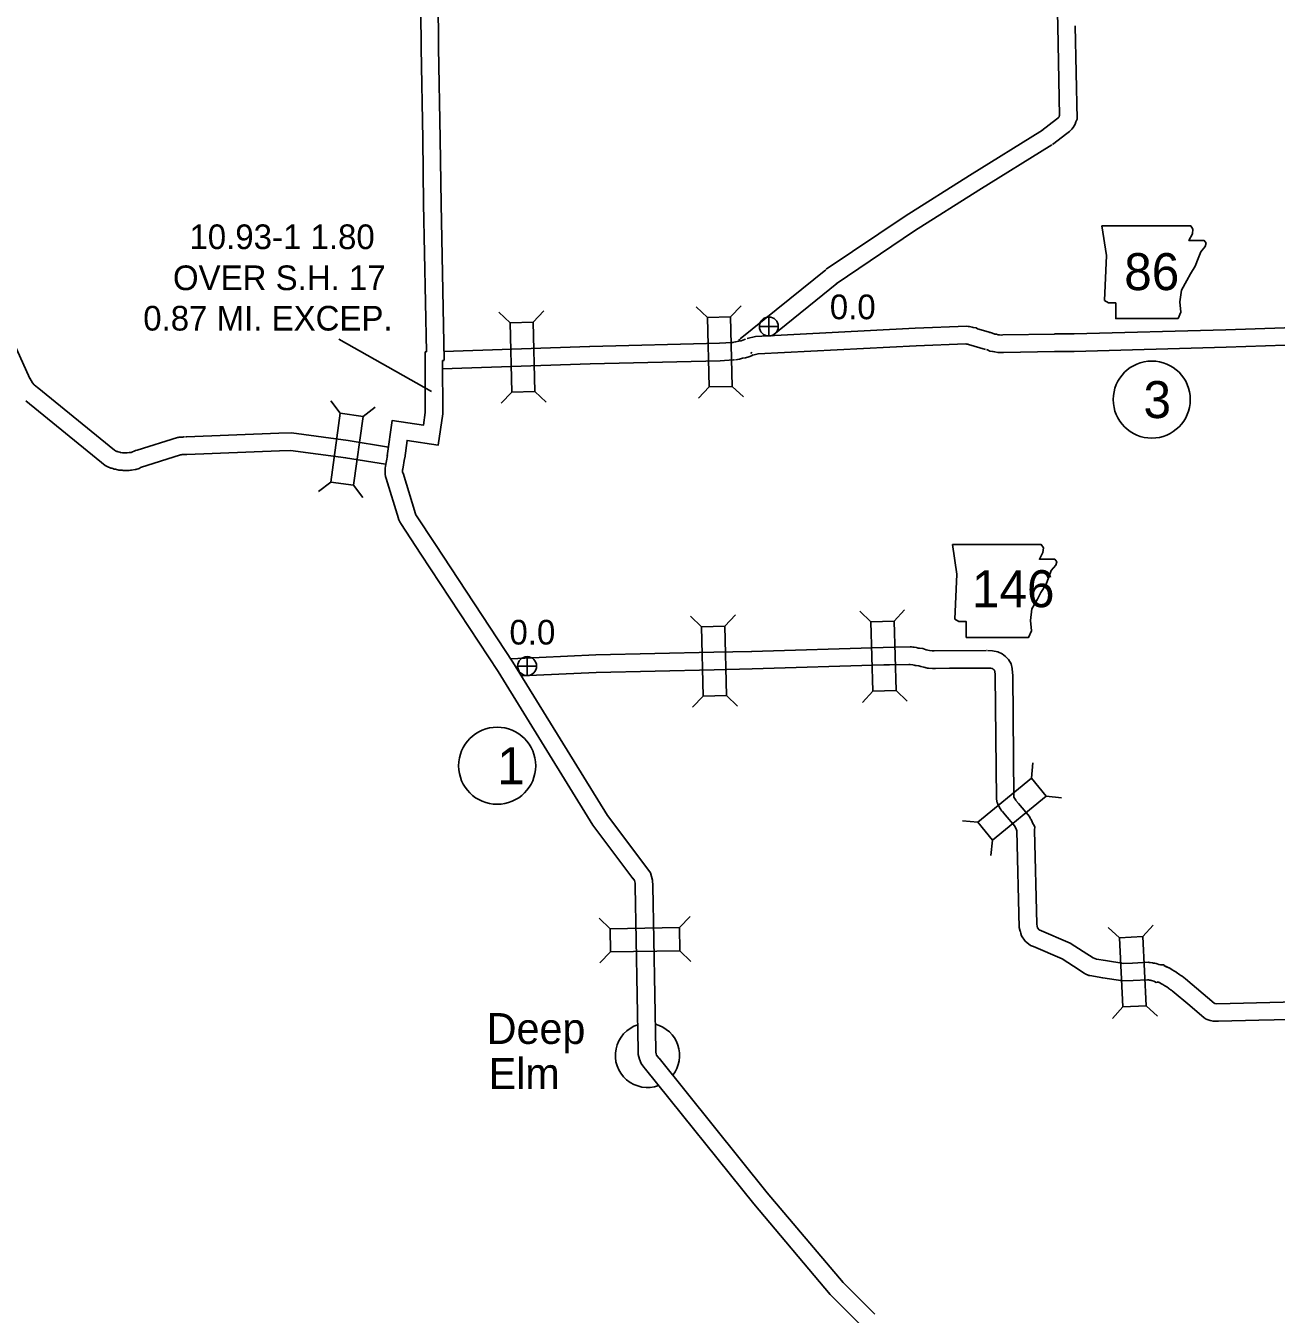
# Model space of a CAD drawing. Extents: x -939622 to -934222, y 1383701 to 1385301.
# Drawn here: x -935986.8 to -935922.6, y 1384037.4 to 1384103.6 of the extents above; entities that cross this region are included whole.
import ezdxf

# ---------------------------------------------------------------- set-up
doc = ezdxf.new("R2010")
doc.units = 0
for name, color, linetype in [('Level 10', 7, 'Continuous'), ('Level 20', 7, 'Continuous'), ('Level 21', 7, 'Continuous'), ('Level 24', 7, 'Continuous'), ('Level 25', 7, 'Continuous'), ('Level 26', 7, 'Continuous'), ('Level 27', 7, 'Continuous')]:
    doc.layers.add(name, color=color, linetype=linetype)

msp = doc.modelspace()

# ---------------------------------------------------------------- linework, layer by layer
at = {"layer": 'Level 10'}
for points in [[(-935967.253, 1384133.883), (-935967.135, 1384126.48), (-935967.016, 1384118.358), (-935966.906, 1384111.276), (-935966.879, 1384111.03), (-935966.83, 1384110.842), (-935966.763, 1384110.636), (-935966.627, 1384110.219), (-935966.564, 1384110.085), (-935966.549, 1384110.036), (-935966.548, 1384110.028), (-935966.487, 1384102.503), (-935966.407, 1384097.812)], [(-935966.353, 1384133.862), (-935966.235, 1384126.493), (-935966.116, 1384118.371), (-935966.007, 1384111.332), (-935965.992, 1384111.194), (-935965.966, 1384111.096), (-935965.907, 1384110.915), (-935965.789, 1384110.551), (-935965.724, 1384110.413), (-935965.659, 1384110.205), (-935965.649, 1384110.064), (-935965.587, 1384102.514), (-935965.508, 1384097.827)], [(-935934.839, 1384110.377), (-935934.19, 1384110.413), (-935934.182, 1384110.412), (-935934.131, 1384110.397), (-935934.121, 1384110.391), (-935934.057, 1384110.358), (-935934.035, 1384110.346), (-935934.021, 1384110.334), (-935933.992, 1384110.308), (-935933.978, 1384110.293), (-935933.962, 1384110.244), (-935933.796, 1384103.612)], [(-935933.705, 1384099.012), (-935933.796, 1384103.614)], [(-935932.802, 1384098.843), (-935932.896, 1384103.632)], [(-935933.705, 1384099.012), (-935933.711, 1384098.999), (-935933.724, 1384098.957), (-935933.747, 1384098.92), (-935933.767, 1384098.893), (-935933.779, 1384098.88), (-935933.853, 1384098.829), (-935934.611, 1384098.251)], [(-935932.802, 1384098.843), (-935932.864, 1384098.692), (-935932.9, 1384098.576), (-935933.003, 1384098.411), (-935933.07, 1384098.322), (-935933.181, 1384098.199), (-935933.324, 1384098.1), (-935934.065, 1384097.535)], [(-935945.679, 1384091.122), (-935941.636, 1384093.852), (-935938.321, 1384095.947), (-935934.576, 1384098.275)], [(-935966.407, 1384097.813), (-935966.363, 1384094.479), (-935966.215, 1384086.877)], [(-935965.508, 1384097.825), (-935965.463, 1384094.493), (-935965.306, 1384086.451)], [(-935945.175, 1384090.376), (-935941.144, 1384093.099), (-935937.843, 1384095.185), (-935934.101, 1384097.511)], [(-935990.218, 1384093.549), (-935986.575, 1384085.52)], [(-935950.094, 1384087.547), (-935945.71, 1384091.098)], [(-935948.465, 1384087.708), (-935945.144, 1384090.399)], [(-935949.743, 1384087.568), (-935949.312, 1384087.676), (-935941.106, 1384088.091), (-935938.453, 1384088.194), (-935938.397, 1384088.185), (-935938.329, 1384088.186), (-935938.194, 1384088.149), (-935938.138, 1384088.136), (-935937.989, 1384088.115), (-935937.917, 1384088.071), (-935937.24, 1384087.871)], [(-935933.96, 1384087.8), (-935932.955, 1384087.802), (-935925.168, 1384088.014), (-935919.137, 1384088.222), (-935918.204, 1384088.317), (-935916.892, 1384088.389), (-935908.778, 1384088.578), (-935902.771, 1384088.246), (-935902.143, 1384088.133), (-935901.804, 1384088.026)], [(-935957.829, 1384087.159), (-935951.161, 1384087.327), (-935950.509, 1384087.363), (-935950.456, 1384087.367)], [(-935949.827, 1384087.537), (-935949.878, 1384087.513), (-935949.96, 1384087.482), (-935950.042, 1384087.456), (-935950.169, 1384087.435), (-935950.335, 1384087.394), (-935950.51, 1384087.359)], [(-935950.181, 1384087.463), (-935950.159, 1384087.489), (-935950.114, 1384087.53)], [(-935937.289, 1384087.882), (-935937.195, 1384087.865), (-935937.051, 1384087.808), (-935937.018, 1384087.793), (-935937.015, 1384087.793), (-935936.936, 1384087.783), (-935936.856, 1384087.763), (-935936.781, 1384087.752), (-935936.693, 1384087.746), (-935936.616, 1384087.752), (-935933.967, 1384087.799)], [(-935933.957, 1384086.9), (-935932.942, 1384086.902), (-935925.14, 1384087.115), (-935919.076, 1384087.324), (-935918.134, 1384087.419), (-935916.857, 1384087.489), (-935908.793, 1384087.678), (-935902.876, 1384087.351), (-935902.359, 1384087.257), (-935902.074, 1384087.168)], [(-935968.222, 1384081.534), (-935967.98, 1384083.354), (-935966.367, 1384083.113), (-935966.274, 1384083.76), (-935966.287, 1384086.875)], [(-935966.216, 1384086.877), (-935966.287, 1384086.875)], [(-935957.833, 1384087.158), (-935965.315, 1384086.907)], [(-935949.439, 1384086.725), (-935949.524, 1384086.684), (-935949.665, 1384086.631), (-935949.831, 1384086.579), (-935949.987, 1384086.553), (-935950.14, 1384086.515), (-935950.337, 1384086.476)], [(-935949.547, 1384086.792), (-935949.502, 1384086.87)], [(-935949.523, 1384086.695), (-935949.178, 1384086.782), (-935941.066, 1384087.192), (-935938.506, 1384087.291), (-935938.459, 1384087.284), (-935938.443, 1384087.284), (-935938.415, 1384087.276), (-935938.368, 1384087.265), (-935937.495, 1384087.008)], [(-935937.447, 1384086.996), (-935937.443, 1384086.995), (-935937.399, 1384086.978), (-935937.275, 1384086.924), (-935937.146, 1384086.902), (-935937.104, 1384086.897), (-935937.028, 1384086.878), (-935936.874, 1384086.856), (-935936.687, 1384086.844), (-935936.571, 1384086.853), (-935933.951, 1384086.9)], [(-935967.33, 1384081.416), (-935967.208, 1384082.329), (-935965.604, 1384082.089), (-935965.373, 1384083.698), (-935965.385, 1384086.442)], [(-935957.803, 1384086.259), (-935965.399, 1384086.004)], [(-935965.306, 1384086.444), (-935965.385, 1384086.442)], [(-935957.807, 1384086.259), (-935951.124, 1384086.427), (-935950.452, 1384086.465), (-935950.391, 1384086.469)], [(-935986.583, 1384085.538), (-935986.516, 1384085.406), (-935986.449, 1384085.298), (-935986.351, 1384085.191), (-935986.192, 1384085.046)], [(-935986.212, 1384085.063), (-935982.241, 1384081.826), (-935982.179, 1384081.796), (-935982.109, 1384081.766), (-935982.072, 1384081.755), (-935982.041, 1384081.747), (-935982.033, 1384081.744), (-935981.958, 1384081.724), (-935981.931, 1384081.716), (-935981.819, 1384081.703), (-935981.8, 1384081.696), (-935981.779, 1384081.695), (-935981.764, 1384081.694), (-935981.758, 1384081.694), (-935981.727, 1384081.694), (-935981.643, 1384081.69), (-935981.583, 1384081.691), (-935981.485, 1384081.707), (-935981.478, 1384081.705), (-935981.421, 1384081.706), (-935981.374, 1384081.716), (-935981.152, 1384081.814), (-935981.149, 1384081.814), (-935981.076, 1384081.824), (-935979.001, 1384082.483), (-935978.958, 1384082.484), (-935978.904, 1384082.494), (-935978.862, 1384082.495), (-935978.835, 1384082.497), (-935978.791, 1384082.501), (-935978.737, 1384082.506), (-935978.719, 1384082.506), (-935978.674, 1384082.512), (-935978.631, 1384082.51)], [(-935986.78, 1384084.365), (-935982.706, 1384081.044), (-935982.609, 1384080.987), (-935982.422, 1384080.91), (-935982.392, 1384080.911), (-935982.368, 1384080.905), (-935982.323, 1384080.89), (-935982.312, 1384080.887), (-935982.243, 1384080.862), (-935982.202, 1384080.857), (-935982.19, 1384080.854), (-935982.019, 1384080.809), (-935981.866, 1384080.798), (-935981.856, 1384080.798), (-935981.84, 1384080.797), (-935981.788, 1384080.793), (-935981.742, 1384080.794), (-935981.658, 1384080.79), (-935981.655, 1384080.79), (-935981.541, 1384080.782), (-935981.475, 1384080.796), (-935981.416, 1384080.8), (-935981.368, 1384080.801), (-935981.166, 1384080.839), (-935981.159, 1384080.841), (-935981.132, 1384080.846), (-935980.972, 1384080.893), (-935980.923, 1384080.928), (-935980.905, 1384080.934), (-935978.837, 1384081.591), (-935978.812, 1384081.596), (-935978.756, 1384081.601), (-935978.71, 1384081.605), (-935978.686, 1384081.607), (-935978.657, 1384081.607), (-935978.642, 1384081.609), (-935978.594, 1384081.607), (-935978.527, 1384081.616)], [(-935978.594, 1384082.512), (-935978.539, 1384082.513), (-935973.789, 1384082.705), (-935973.144, 1384082.724), (-935970.239, 1384082.328)], [(-935970.228, 1384082.326), (-935968.155, 1384081.992)], [(-935978.577, 1384081.612), (-935978.512, 1384081.613), (-935973.758, 1384081.805), (-935973.192, 1384081.822), (-935970.36, 1384081.436)], [(-935970.371, 1384081.437), (-935968.309, 1384081.105)], [(-935968.219, 1384081.554), (-935968.316, 1384081.008)], [(-935967.333, 1384081.396), (-935967.431, 1384080.85)], [(-935968.319, 1384080.994), (-935968.329, 1384080.923), (-935968.338, 1384080.817), (-935968.339, 1384080.711), (-935968.334, 1384080.604), (-935968.309, 1384080.486), (-935968.279, 1384080.385)], [(-935967.428, 1384080.863), (-935967.435, 1384080.821), (-935967.438, 1384080.777), (-935967.439, 1384080.728), (-935967.438, 1384080.718), (-935967.436, 1384080.706), (-935967.416, 1384080.64)], [(-935968.278, 1384080.38), (-935967.648, 1384078.33), (-935967.643, 1384078.308), (-935967.627, 1384078.247), (-935967.587, 1384078.149), (-935967.554, 1384078.095), (-935967.535, 1384078.058), (-935966.506, 1384076.494)], [(-935967.417, 1384080.645), (-935966.777, 1384078.559), (-935966.774, 1384078.544), (-935966.758, 1384078.514), (-935965.754, 1384076.989)], [(-935965.754, 1384076.989), (-935961.773, 1384070.939), (-935956.919, 1384063.07), (-935954.893, 1384060.376)], [(-935966.506, 1384076.494), (-935962.532, 1384070.455), (-935957.664, 1384062.562), (-935955.612, 1384059.835)], [(-935951.456, 1384071.447), (-935949.511, 1384071.491)], [(-935949.515, 1384071.491), (-935942.756, 1384071.7), (-935942.175, 1384071.717), (-935941.364, 1384071.733), (-935941.311, 1384071.722), (-935941.239, 1384071.718), (-935941.164, 1384071.711), (-935941.053, 1384071.693), (-935941.021, 1384071.678), (-935940.998, 1384071.672), (-935940.971, 1384071.668), (-935940.934, 1384071.663), (-935940.9, 1384071.657), (-935940.723, 1384071.647), (-935940.551, 1384071.582), (-935940.371, 1384071.54), (-935940.236, 1384071.528), (-935940.217, 1384071.523), (-935940.155, 1384071.524), (-935940.146, 1384071.523), (-935937.475, 1384071.536), (-935937.445, 1384071.537)], [(-935937.397, 1384071.537), (-935937.137, 1384071.524), (-935936.877, 1384071.481), (-935936.64, 1384071.366), (-935936.469, 1384071.225), (-935936.319, 1384071.082), (-935936.189, 1384070.85), (-935936.139, 1384070.613), (-935936.11, 1384070.388), (-935936.105, 1384070.272)], [(-935961.881, 1384071.12), (-935957.522, 1384071.31), (-935951.456, 1384071.447)], [(-935949.487, 1384070.592), (-935942.729, 1384070.801), (-935942.439, 1384070.809), (-935941.448, 1384070.828), (-935941.439, 1384070.828), (-935941.436, 1384070.828), (-935941.425, 1384070.828), (-935941.371, 1384070.82), (-935941.366, 1384070.82), (-935941.23, 1384070.802), (-935941.174, 1384070.789), (-935941.106, 1384070.778), (-935941.064, 1384070.772), (-935940.919, 1384070.749), (-935940.878, 1384070.738), (-935940.829, 1384070.726), (-935940.669, 1384070.68), (-935940.478, 1384070.642), (-935940.437, 1384070.642), (-935940.221, 1384070.622), (-935940.22, 1384070.623), (-935940.183, 1384070.623), (-935940.063, 1384070.613), (-935939.354, 1384070.627), (-935937.447, 1384070.636), (-935937.395, 1384070.639)], [(-935961.338, 1384070.243), (-935957.493, 1384070.41), (-935951.436, 1384070.547)], [(-935951.436, 1384070.547), (-935949.491, 1384070.592)], [(-935937.442, 1384070.639), (-935937.234, 1384070.628), (-935937.154, 1384070.615), (-935937.129, 1384070.602), (-935937.066, 1384070.551), (-935937.041, 1384070.527), (-935937.027, 1384070.462), (-935937.007, 1384070.311), (-935937.004, 1384070.236)], [(-935937.005, 1384070.25), (-935936.938, 1384063.929), (-935936.928, 1384063.801), (-935936.897, 1384063.723), (-935936.891, 1384063.702), (-935936.851, 1384063.597), (-935936.81, 1384063.541), (-935936.749, 1384063.424), (-935936.708, 1384063.366), (-935936.675, 1384063.313), (-935936.627, 1384063.266), (-935936.491, 1384063.1), (-935936.002, 1384062.524), (-935935.907, 1384062.321), (-935935.893, 1384062.281), (-935935.771, 1384057.317), (-935935.73, 1384057.12), (-935935.709, 1384057.095), (-935935.687, 1384057.023), (-935935.685, 1384057.011), (-935935.656, 1384056.891), (-935935.459, 1384056.606), (-935935.373, 1384056.539), (-935935.191, 1384056.386), (-935935.04, 1384056.342), (-935933.57, 1384055.71), (-935932.979, 1384055.33)], [(-935936.105, 1384070.259), (-935936.039, 1384064.014), (-935935.941, 1384063.856), (-935935.936, 1384063.843), (-935935.799, 1384063.676), (-935935.239, 1384063.014), (-935935.185, 1384062.9), (-935935.16, 1384062.861), (-935935.104, 1384062.742), (-935935.102, 1384062.726), (-935934.971, 1384062.487), (-935934.994, 1384062.305), (-935934.874, 1384057.481), (-935934.857, 1384057.384), (-935934.83, 1384057.297), (-935934.752, 1384057.2), (-935934.744, 1384057.194), (-935933.146, 1384056.508), (-935932.492, 1384056.087)], [(-935954.888, 1384060.369), (-935954.709, 1384060.122), (-935954.605, 1384059.736), (-935954.587, 1384059.46)], [(-935955.617, 1384059.841), (-935955.535, 1384059.727), (-935955.497, 1384059.589), (-935955.486, 1384059.404)], [(-935955.486, 1384059.424), (-935955.439, 1384056.676)], [(-935954.586, 1384059.44), (-935954.539, 1384056.691)], [(-935955.439, 1384056.676), (-935955.341, 1384050.992)], [(-935954.539, 1384056.691), (-935954.441, 1384051.008)], [(-935928.204, 1384055.264), (-935928.342, 1384055.396), (-935928.506, 1384055.392), (-935928.607, 1384055.419), (-935928.692, 1384055.446), (-935928.732, 1384055.46), (-935928.802, 1384055.475), (-935928.859, 1384055.483), (-935928.879, 1384055.486), (-935928.921, 1384055.497), (-935929.054, 1384055.517), (-935929.079, 1384055.516), (-935929.099, 1384055.518), (-935929.145, 1384055.525), (-935929.957, 1384055.486), (-935930.395, 1384055.467), (-935931.335, 1384055.612), (-935931.798, 1384055.693), (-935931.967, 1384055.745), (-935932.49, 1384056.086)], [(-935928.585, 1384054.495), (-935928.59, 1384054.496), (-935928.591, 1384054.495), (-935928.74, 1384054.492), (-935928.818, 1384054.541), (-935928.854, 1384054.554), (-935928.971, 1384054.59), (-935928.98, 1384054.591), (-935928.992, 1384054.593), (-935929.043, 1384054.598), (-935929.105, 1384054.614), (-935929.12, 1384054.617), (-935929.183, 1384054.622), (-935929.916, 1384054.587), (-935930.444, 1384054.564), (-935931.482, 1384054.724), (-935932.147, 1384054.84), (-935932.191, 1384054.851), (-935932.234, 1384054.864), (-935932.348, 1384054.907), (-935932.376, 1384054.934), (-935932.428, 1384054.971), (-935932.981, 1384055.331)], [(-935918.118, 1384053.574), (-935925.627, 1384053.395), (-935925.711, 1384053.405), (-935925.723, 1384053.408), (-935925.764, 1384053.421), (-935927.223, 1384054.677), (-935927.32, 1384054.738), (-935927.4, 1384054.805), (-935927.465, 1384054.843), (-935927.476, 1384054.85), (-935927.492, 1384054.859), (-935927.506, 1384054.868), (-935927.52, 1384054.877), (-935927.702, 1384055.022), (-935927.719, 1384055.029), (-935927.833, 1384055.087), (-935927.835, 1384055.088), (-935927.881, 1384055.125), (-935927.913, 1384055.14), (-935927.989, 1384055.195), (-935928.07, 1384055.239), (-935928.089, 1384055.244), (-935928.147, 1384055.275), (-935928.23, 1384055.306), (-935928.265, 1384055.323), (-935928.28, 1384055.328), (-935928.342, 1384055.354)], [(-935917.985, 1384052.677), (-935923.46, 1384052.546), (-935925.539, 1384052.495), (-935925.56, 1384052.495), (-935925.661, 1384052.492), (-935925.724, 1384052.5), (-935925.731, 1384052.5), (-935925.813, 1384052.498), (-935925.883, 1384052.519), (-935925.968, 1384052.541), (-935926.162, 1384052.601), (-935926.27, 1384052.67), (-935927.01, 1384053.306), (-935927.919, 1384054.066), (-935927.933, 1384054.074), (-935927.94, 1384054.079), (-935927.955, 1384054.087), (-935927.996, 1384054.113), (-935928.033, 1384054.137), (-935928.087, 1384054.174), (-935928.111, 1384054.198), (-935928.186, 1384054.257), (-935928.293, 1384054.311), (-935928.401, 1384054.385), (-935928.621, 1384054.495), (-935928.688, 1384054.523)], [(-935955.34, 1384050.98), (-935955.332, 1384050.787), (-935955.275, 1384050.545), (-935955.184, 1384050.327), (-935955.047, 1384050.13), (-935954.967, 1384050.032)], [(-935954.441, 1384051.019), (-935954.437, 1384050.911), (-935954.416, 1384050.824), (-935954.39, 1384050.762), (-935954.328, 1384050.672), (-935954.271, 1384050.603)], [(-935954.268, 1384050.599), (-935948.707, 1384043.688), (-935944.812, 1384039.069), (-935943.192, 1384037.446)], [(-935954.97, 1384050.035), (-935949.402, 1384043.116), (-935945.476, 1384038.46), (-935943.829, 1384036.81)]]:
    msp.add_lwpolyline(points, dxfattribs=at)
at = {"layer": 'Level 20'}
for p, q in [((-935961.921, 1384088.377), (-935962.495, 1384088.922)), ((-935960.734, 1384088.407), (-935960.188, 1384088.981)), ((-935951.781, 1384088.644), (-935952.355, 1384089.189)), ((-935950.594, 1384088.674), (-935950.048, 1384089.247)), ((-935961.832, 1384084.814), (-935962.377, 1384084.24)), ((-935960.644, 1384084.844), (-935960.07, 1384084.298)), ((-935951.691, 1384085.081), (-935952.237, 1384084.507)), ((-935950.504, 1384085.111), (-935949.93, 1384084.565)), ((-935970.647, 1384083.728), (-935971.126, 1384084.358)), ((-935969.47, 1384083.567), (-935968.84, 1384084.046)), ((-935971.129, 1384080.196), (-935971.759, 1384079.717)), ((-935969.952, 1384080.036), (-935969.472, 1384079.405)), ((-935943.388, 1384073.014), (-935943.964, 1384073.558)), ((-935942.201, 1384073.049), (-935941.657, 1384073.625)), ((-935952.08, 1384072.765), (-935952.653, 1384073.313)), ((-935950.893, 1384072.792), (-935950.346, 1384073.365)), ((-935942.096, 1384069.487), (-935941.52, 1384068.943)), ((-935952, 1384069.202), (-935952.547, 1384068.63)), ((-935950.812, 1384069.229), (-935950.239, 1384068.682)), ((-935943.284, 1384069.452), (-935943.827, 1384068.876)), ((-935935.142, 1384064.976), (-935935.064, 1384065.764)), ((-935934.39, 1384064.057), (-935933.602, 1384063.978)), ((-935937.9, 1384062.719), (-935938.688, 1384062.797)), ((-935937.147, 1384061.799), (-935937.226, 1384061.011)), ((-935956.781, 1384057.247), (-935957.351, 1384057.797)), ((-935953.217, 1384057.308), (-935952.667, 1384057.878)), ((-935930.616, 1384056.788), (-935931.202, 1384057.32)), ((-935929.429, 1384056.845), (-935928.896, 1384057.431)), ((-935956.76, 1384056.059), (-935957.311, 1384055.489)), ((-935953.197, 1384056.12), (-935952.627, 1384055.57)), ((-935930.445, 1384053.228), (-935930.977, 1384052.641)), ((-935929.258, 1384053.285), (-935928.672, 1384052.752))]:
    msp.add_line(p, q, dxfattribs=at)
for points in [[(-935951.781, 1384088.644), (-935951.691, 1384085.081), (-935950.504, 1384085.111), (-935950.594, 1384088.674)], [(-935961.921, 1384088.377), (-935961.832, 1384084.814), (-935960.644, 1384084.844), (-935960.734, 1384088.407)], [(-935970.647, 1384083.728), (-935971.129, 1384080.196), (-935969.952, 1384080.036), (-935969.47, 1384083.567)], [(-935952.08, 1384072.765), (-935952, 1384069.202), (-935950.812, 1384069.229), (-935950.893, 1384072.792)], [(-935942.096, 1384069.487), (-935942.201, 1384073.049), (-935943.388, 1384073.014), (-935943.284, 1384069.452)], [(-935935.142, 1384064.976), (-935937.9, 1384062.719), (-935937.147, 1384061.799), (-935934.39, 1384064.057)], [(-935953.217, 1384057.308), (-935956.781, 1384057.247), (-935956.76, 1384056.059), (-935953.197, 1384056.12)], [(-935929.258, 1384053.285), (-935929.429, 1384056.845), (-935930.616, 1384056.788), (-935930.445, 1384053.228)]]:
    msp.add_lwpolyline(points, close=True, dxfattribs=at)
at = {"layer": 'Level 21'}
for points in [[(-935931.524, 1384093.358), (-935931.296, 1384091.836), (-935931.397, 1384089.527), (-935931.194, 1384089.4), (-935930.814, 1384089.4), (-935930.814, 1384088.588), (-935927.616, 1384088.588), (-935927.464, 1384088.917), (-935927.515, 1384089.45), (-935927.438, 1384090.059), (-935927.159, 1384090.542), (-935926.982, 1384090.897), (-935926.728, 1384091.278), (-935926.576, 1384091.684), (-935926.449, 1384092.013), (-935926.22, 1384092.293), (-935926.17, 1384092.47), (-935926.271, 1384092.597), (-935927.058, 1384092.597), (-935926.88, 1384092.952), (-935926.855, 1384093.181), (-935926.96, 1384093.356)], [(-935939.201, 1384076.987), (-935938.972, 1384075.464), (-935939.074, 1384073.155), (-935938.871, 1384073.028), (-935938.49, 1384073.028), (-935938.49, 1384072.216), (-935935.293, 1384072.216), (-935935.14, 1384072.546), (-935935.191, 1384073.079), (-935935.115, 1384073.688), (-935934.836, 1384074.17), (-935934.658, 1384074.525), (-935934.404, 1384074.906), (-935934.252, 1384075.312), (-935934.125, 1384075.642), (-935933.897, 1384075.921), (-935933.846, 1384076.099), (-935933.948, 1384076.226), (-935934.734, 1384076.226), (-935934.557, 1384076.581), (-935934.531, 1384076.809), (-935934.636, 1384076.985)]]:
    msp.add_lwpolyline(points, close=True, dxfattribs=at)
at = {"layer": 'Level 24'}
for start, end in [(107.426, 290.27933), (321.81966, 75.60613)]:
    msp.add_arc((-935954.861, 1384050.742), 1.65, start, end, dxfattribs=at)
at = {"layer": 'Level 25'}
msp.add_lwpolyline([(-935970.705, 1384087.528), (-935965.951, 1384084.85)], dxfattribs=at)
at = {"layer": 'Level 26'}
for p, q in [((-935948.629, 1384087.697), (-935948.629, 1384088.672)), ((-935949.116, 1384088.184), (-935948.141, 1384088.184)), ((-935961.044, 1384070.253), (-935961.044, 1384071.228)), ((-935961.532, 1384070.741), (-935960.557, 1384070.741))]:
    msp.add_line(p, q, dxfattribs=at)
for centre in [(-935948.629, 1384088.184), (-935961.044, 1384070.741)]:
    msp.add_circle(centre, 0.487, dxfattribs=at)
at = {"layer": 'Level 27'}
for centre in [(-935928.963, 1384084.431), (-935962.581, 1384065.621)]:
    msp.add_circle(centre, 1.98, dxfattribs=at)

# ---------------------------------------------------------------- texts
at = {"layer": 'Level 21'}
for s, p in [('86', (-935930.378, 1384090.053)), ('146', (-935938.2, 1384073.765))]:
    msp.add_text(s, height=1.9008, dxfattribs=at).set_placement(p)
at = {"layer": 'Level 24'}
for s, p in [('Deep', (-935963.116, 1384051.33)), ('Elm', (-935963.018, 1384049.019))]:
    msp.add_text(s, height=1.584, dxfattribs=at).set_placement(p)
at = {"layer": 'Level 25'}
for s, p in [('10.93-1 1.80', (-935978.385, 1384092.16)), ('OVER S.H. 17', (-935979.232, 1384090.053)), ('0.0', (-935945.498, 1384088.558)), ('0.87 MI. EXCEP.', (-935980.758, 1384087.977)), ('0.0', (-935961.95, 1384071.848))]:
    msp.add_text(s, height=1.2672, dxfattribs=at).set_placement(p)
at = {"layer": 'Level 27'}
for s, p in [('3', (-935929.388, 1384083.48)), ('1', (-935962.581, 1384064.671))]:
    msp.add_text(s, height=1.901, dxfattribs=at).set_placement(p)

doc.saveas('drawing.dxf')
